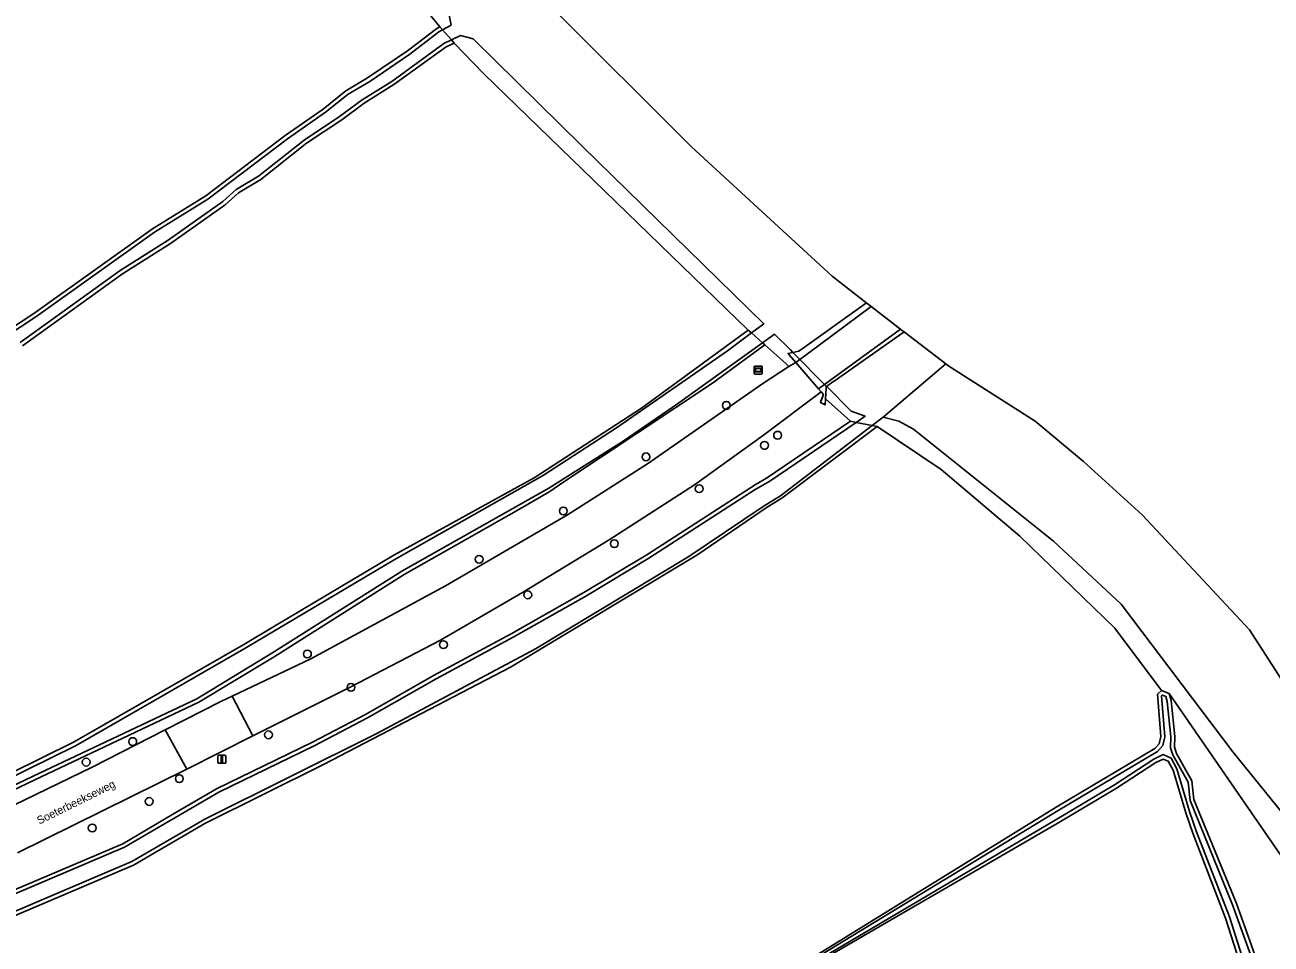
# Model space of a CAD drawing. Extents: x 162396 to 163643, y 386452 to 387406.
# Drawn here: x 163407.9 to 163563.6, y 386571.8 to 386686.7 of the extents above; entities that cross this region are included whole.
import ezdxf

# ---------------------------------------------------------------- set-up
doc = ezdxf.new("R2010")
doc.units = 0
for name, color, linetype in [('IMGEO_Berm_groen', 7, 'Continuous'), ('IMGEO_Boom', 7, 'Continuous'), ('IMGEO_Greppel_droge_sloot', 7, 'Continuous'), ('IMGEO_Lichtmast', 7, 'Continuous'), ('IMGEO_Loofbos', 7, 'Continuous'), ('IMGEO_Oever', 7, 'Continuous'), ('IMGEO_Openbare_ruimte_label', 7, 'Continuous'), ('IMGEO_Rijbaan_lokaal_gesloten', 7, 'Continuous'), ('IMGEO_Rijbaan_lokaal_open', 7, 'Continuous'), ('IMGEO_Rivier', 7, 'Continuous'), ('IMGEO_Terreindeel_gesloten', 7, 'Continuous'), ('IMGEO_Waterloop', 7, 'Continuous'), ('IMGEO_Wegwijzer', 7, 'Continuous')]:
    doc.layers.add(name, color=color, linetype=linetype)

msp = doc.modelspace()

# ---------------------------------------------------------------- linework, layer by layer
at = {"layer": 'IMGEO_Berm_groen'}
for points in [[(163405.11, 386588.52), (163416.26, 386593.91), (163425.38, 386598.57), (163432.36, 386602.14), (163433.75, 386602.8), (163443.58, 386607.46), (163460.42, 386616.57), (163475.67, 386625.45), (163485.67, 386631.81), (163500.08, 386641.88), (163503.35, 386643.97), (163502.95, 386644.35), (163500.35, 386646.68), (163493.79, 386641.9), (163475.22, 386629.59), (163473.48, 386628.39), (163469.61, 386626.14), (163455.26, 386617.99), (163439.01, 386607.73), (163429.6, 386602.04), (163409.1, 386592.34), (163397.9, 386587.01)], [(163401.51, 386576.46), (163420.09, 386584.36), (163426.24, 386587.96), (163431.82, 386591.22), (163443.79, 386597.04), (163450.45, 386600.52), (163459.01, 386605.41), (163468.63, 386610.6), (163477.72, 386615.74), (163485.57, 386620.45), (163499.26, 386629.28), (163500.56, 386630.02), (163511.05, 386637.15), (163507.93, 386639.95), (163507.88, 386639.21), (163507.28, 386639.5), (163507.65, 386640.51), (163507.39, 386640.81), (163500.18, 386635.41), (163491.54, 386629.21), (163480.87, 386622.34), (163470.05, 386615.73), (163459.8, 386609.81), (163448.52, 386603.94), (163436.36, 386597.86), (163428.09, 386593.69), (163406.94, 386583.2)]]:
    msp.add_lwpolyline(points, dxfattribs=at)
at = {"layer": 'IMGEO_Boom'}
for centre in [(163495.52, 386639.13), (163501.93, 386635.4), (163485.49, 386632.7), (163500.29, 386634.13), (163492.13, 386628.72), (163475.16, 386625.93), (163481.52, 386621.85), (163464.63, 386619.9), (163470.71, 386615.46), (163443.17, 386608.07), (163460.17, 386609.23), (163448.61, 386603.9), (163421.34, 386597.12), (163438.3, 386597.97), (163415.52, 386594.55), (163427.17, 386592.49), (163423.4, 386589.64), (163416.28, 386586.33)]:
    msp.add_circle(centre, 0.489, dxfattribs=at)
at = {"layer": 'IMGEO_Greppel_droge_sloot'}
msp.add_lwpolyline([(163562.37, 386566.81), (163558.8, 386576.71), (163553.47, 386589.78), (163553.22, 386592.06), (163551.32, 386595.45), (163551.05, 386596.36), (163551.08, 386597.73), (163550.63, 386602.14), (163550.45, 386602.75), (163550.02, 386602.92), (163549.91, 386602.82), (163550.34, 386597.72), (163550.07, 386596.62), (163549.41, 386595.88), (163537.01, 386588.49), (163506.56, 386569.96)], dxfattribs=at)
msp.add_lwpolyline([(163455.86, 386538.91), (163459.42, 386541.07), (163473.79, 386549.33), (163480.21, 386553.86), (163490.62, 386559.9), (163500.01, 386565.64), (163504.86, 386568.54), (163536.63, 386587.32), (163544.03, 386591.71), (163548.94, 386594.93), (163550.11, 386595.49), (163551.11, 386595.06), (163551.84, 386593.72), (163553.42, 386588.37), (163554.3, 386585.83), (163558.39, 386575.21), (163562.24, 386563.11), (163561.91, 386561.81), (163543.3, 386550.61), (163516, 386533.9), (163499.96, 386535.01), (163489.08, 386535.89), (163478.15, 386536.57)], close=True, dxfattribs=at)
at = {"layer": 'IMGEO_Lichtmast'}
for p, q in [((163431.99, 386594.51), (163431.99, 386595.31)), ((163431.99, 386595.31), (163431.99, 386594.51)), ((163432.09, 386595.41), (163432.88, 386595.41)), ((163432.88, 386595.41), (163432.09, 386595.41)), ((163432.88, 386594.41), (163432.09, 386594.41)), ((163432.09, 386594.41), (163432.88, 386594.41)), ((163432.98, 386595.31), (163432.98, 386594.51)), ((163432.98, 386594.51), (163432.98, 386595.31))]:
    msp.add_line(p, q, dxfattribs=at)
msp.add_lwpolyline([(163432.41, 386595.29), (163432.56, 386595.29), (163432.56, 386594.54), (163432.41, 386594.54), (163432.41, 386595.29)], dxfattribs=at)
for centre, start, end in [((163432.09, 386595.31), 90, 180), ((163432.09, 386595.31), 90, 180), ((163432.09, 386594.51), 180, 270), ((163432.09, 386594.51), 180, 270), ((163432.88, 386595.31), 0, 90), ((163432.88, 386595.31), 360, 90), ((163432.88, 386594.51), 270, 0), ((163432.88, 386594.51), 270, 0)]:
    msp.add_arc(centre, 0.1, start, end, dxfattribs=at)
at = {"layer": 'IMGEO_Loofbos'}
for points in [[(163391.4, 386639.08), (163408.96, 386650.61), (163423.8, 386661.18), (163430.46, 386665.33), (163440.39, 386672.86), (163445.14, 386676.15), (163447.97, 386678.44), (163450.69, 386680.05), (163455.66, 386683.43), (163459.34, 386686.22), (163459.71, 386686.42), (163457.27, 386689.42)], [(163402.02, 386591.16), (163413.94, 386597.03), (163417.16, 386598.88), (163435.23, 386609.26), (163439.05, 386611.53), (163453.98, 386620.4), (163471.52, 386630.07), (163484.91, 386638.8), (163498.26, 386648.53), (163465.17, 386680.6), (163461.52, 386684.41), (163460.49, 386683.93), (163453.99, 386679.21), (163450.28, 386676.89), (163447.46, 386674.82), (163443.07, 386671.89), (163437.34, 386667.34), (163434.55, 386665.69), (163432.89, 386664.21), (163426.04, 386659.35), (163420.06, 386655.56), (163407.55, 386646.58)], [(163506.44, 386570.22), (163536.75, 386588.92), (163549.09, 386596.27), (163549.61, 386596.86), (163549.83, 386597.76), (163549.39, 386603.03), (163549.92, 386603.5), (163544.07, 386611.28), (163532.19, 386622.81), (163522.36, 386631.11), (163514.36, 386636.48), (163502.48, 386627.54), (163500.63, 386626.43), (163491.82, 386620.43), (163468.54, 386606.44), (163445.2, 386594.24), (163430.35, 386586.89), (163421.44, 386581.67), (163402.62, 386573.67)]]:
    msp.add_lwpolyline(points, dxfattribs=at)
for points in [[(163550.86, 386603.13), (163551.12, 386602.24), (163551.58, 386597.75), (163551.55, 386596.43), (163551.79, 386595.64), (163553.71, 386592.21), (163553.96, 386589.9), (163559.27, 386576.89), (163562.84, 386566.97), (163566.19, 386556.37), (163567.14, 386552.77), (163574.75, 386529.67), (163593.86, 386541.96), (163569.34, 386576.39)], [(163478.18, 386537.07), (163489.12, 386536.39), (163500, 386535.51), (163515.87, 386534.41), (163543.04, 386551.04), (163561.47, 386562.13), (163561.72, 386563.1), (163557.92, 386575.04), (163553.83, 386585.66), (163552.94, 386588.22), (163551.38, 386593.53), (163550.76, 386594.67), (163550.12, 386594.94), (163549.18, 386594.5), (163544.29, 386591.29), (163536.88, 386586.89), (163505.12, 386568.46), (163500, 386565.34), (163490.87, 386559.78), (163480.45, 386553.87), (163473.95, 386549.09), (163459.51, 386540.9), (163456.65, 386539.08)]]:
    msp.add_lwpolyline(points, close=True, dxfattribs=at)
at = {"layer": 'IMGEO_Oever'}
for points in [[(163457.27, 386689.42), (163459.71, 386686.42), (163460.05, 386686.04), (163461.12, 386686.65), (163460.87, 386687.9)], [(163391.68, 386638.67), (163409.24, 386650.2), (163424.08, 386660.77), (163430.74, 386664.92), (163440.68, 386672.45), (163445.44, 386675.75), (163448.26, 386678.03), (163450.96, 386679.62), (163455.96, 386683.02), (163459.61, 386685.8), (163460.05, 386686.04), (163459.71, 386686.42), (163459.34, 386686.22), (163455.66, 386683.43), (163450.69, 386680.05), (163447.97, 386678.44), (163445.14, 386676.15), (163440.39, 386672.86), (163430.46, 386665.33), (163423.8, 386661.18), (163408.96, 386650.61), (163391.4, 386639.08)], [(163407.55, 386646.58), (163420.06, 386655.56), (163426.04, 386659.35), (163432.89, 386664.21), (163434.55, 386665.69), (163437.34, 386667.34), (163443.07, 386671.89), (163447.46, 386674.82), (163450.28, 386676.89), (163453.99, 386679.21), (163460.49, 386683.93), (163461.52, 386684.41), (163461.17, 386684.8), (163460.23, 386684.36), (163453.71, 386679.62), (163450, 386677.31), (163447.18, 386675.23), (163442.78, 386672.29), (163437.06, 386667.76), (163434.26, 386666.1), (163432.58, 386664.6), (163425.76, 386659.77), (163419.78, 386655.97), (163407.28, 386647)], [(163402.22, 386590.71), (163414.18, 386596.59), (163423.97, 386602.22), (163435.48, 386608.82), (163454.24, 386619.97), (163472.54, 386630.34), (163481.79, 386636.31), (163495.67, 386645.94), (163498.66, 386648.18), (163498.26, 386648.53), (163484.91, 386638.8), (163471.52, 386630.07), (163453.98, 386620.4), (163439.05, 386611.53), (163435.23, 386609.26), (163417.16, 386598.88), (163413.94, 386597.03), (163402.02, 386591.16)], [(163397.9, 386587.01), (163409.1, 386592.34), (163429.6, 386602.04), (163439.01, 386607.73), (163455.26, 386617.99), (163469.61, 386626.14), (163473.48, 386628.39), (163475.22, 386629.59), (163493.79, 386641.9), (163500.35, 386646.68), (163500.04, 386646.96), (163489.41, 386639.33), (163482.61, 386634.67), (163473.36, 386628.8), (163454.99, 386618.41), (163438.74, 386608.16), (163429.36, 386602.48), (163408.88, 386592.79), (163397.7, 386587.47)], [(163401.7, 386576), (163420.31, 386583.91), (163432.08, 386590.79), (163444.02, 386596.59), (163450.69, 386600.08), (163459.25, 386604.97), (163468.87, 386610.16), (163477.97, 386615.31), (163485.83, 386620.03), (163499.13, 386628.6), (163500.95, 386629.68), (163511.73, 386637.01), (163511.05, 386637.15), (163500.56, 386630.02), (163499.26, 386629.28), (163485.57, 386620.45), (163477.72, 386615.74), (163468.63, 386610.6), (163459.01, 386605.41), (163450.45, 386600.52), (163443.79, 386597.04), (163431.82, 386591.22), (163426.24, 386587.96), (163420.09, 386584.36), (163401.51, 386576.46)], [(163402.62, 386573.67), (163421.44, 386581.67), (163430.35, 386586.89), (163445.2, 386594.24), (163468.54, 386606.44), (163491.82, 386620.43), (163500.63, 386626.43), (163502.48, 386627.54), (163514.36, 386636.48), (163513.76, 386636.6), (163502.29, 386627.82), (163500.45, 386626.7), (163500, 386626.4), (163490.83, 386620.24), (163471.67, 386608.7), (163451.85, 386598.12), (163430.36, 386587.44), (163421.21, 386582.12), (163402.44, 386574.14)], [(163562.84, 386566.97), (163559.27, 386576.89), (163553.96, 386589.9), (163553.71, 386592.21), (163551.79, 386595.64), (163551.55, 386596.43), (163551.58, 386597.75), (163551.12, 386602.24), (163550.86, 386603.13), (163549.92, 386603.5), (163549.39, 386603.03), (163549.83, 386597.76), (163549.61, 386596.86), (163549.09, 386596.27), (163536.75, 386588.92), (163506.44, 386570.22)], [(163506.56, 386569.96), (163537.01, 386588.49), (163549.41, 386595.88), (163550.07, 386596.62), (163550.34, 386597.72), (163549.91, 386602.82), (163550.02, 386602.92), (163550.45, 386602.75), (163550.63, 386602.14), (163551.08, 386597.73), (163551.05, 386596.36), (163551.32, 386595.45), (163553.22, 386592.06), (163553.47, 386589.78), (163558.8, 386576.71), (163562.37, 386566.81)]]:
    msp.add_lwpolyline(points, dxfattribs=at)
for points in [[(163463.9, 386684.93), (163462.31, 386685.33), (163461.17, 386684.8), (163461.52, 386684.41), (163465.17, 386680.6), (163498.26, 386648.53), (163498.66, 386648.18), (163500.21, 386649.34), (163477.47, 386671.58)], [(163501.54, 386648.03), (163500.04, 386646.96), (163500.35, 386646.68), (163502.95, 386644.35), (163503.35, 386643.97), (163504.2, 386644.51), (163507.05, 386641.2), (163507.39, 386640.81), (163507.65, 386640.51), (163507.28, 386639.5), (163507.88, 386639.21), (163507.93, 386639.95), (163511.05, 386637.15), (163511.73, 386637.01), (163512.86, 386637.78), (163511.14, 386638.39), (163508.08, 386641.49), (163508.06, 386641.51), (163503.85, 386645.76), (163503.55, 386646.07)], [(163518.9, 386636.15), (163517.08, 386637.18), (163515.13, 386637.65), (163513.76, 386636.6), (163514.36, 386636.48), (163522.36, 386631.11), (163532.19, 386622.81), (163544.07, 386611.28), (163549.92, 386603.5), (163550.86, 386603.13), (163569.34, 386576.39), (163593.86, 386541.96), (163594.43, 386541.13), (163605.08, 386527.79), (163605.32, 386525.72), (163612.1, 386524.92), (163587.38, 386560.56), (163558.82, 386595.86), (163544.88, 386614.29), (163536.39, 386622.18)], [(163455.86, 386538.91), (163478.15, 386536.57), (163489.08, 386535.89), (163499.96, 386535.01), (163516, 386533.9), (163543.3, 386550.61), (163561.91, 386561.81), (163562.24, 386563.11), (163558.39, 386575.21), (163554.3, 386585.83), (163553.42, 386588.37), (163551.84, 386593.72), (163551.11, 386595.06), (163550.11, 386595.49), (163548.94, 386594.93), (163544.03, 386591.71), (163536.63, 386587.32), (163504.86, 386568.54), (163500.01, 386565.64), (163490.62, 386559.9), (163480.21, 386553.86), (163473.79, 386549.33), (163459.42, 386541.07)], [(163561.72, 386563.1), (163561.47, 386562.13), (163543.04, 386551.04), (163515.87, 386534.41), (163500, 386535.51), (163489.12, 386536.39), (163478.18, 386537.07), (163456.65, 386539.08), (163459.51, 386540.9), (163473.95, 386549.09), (163480.45, 386553.87), (163490.87, 386559.78), (163500, 386565.34), (163505.12, 386568.46), (163536.88, 386586.89), (163544.29, 386591.29), (163549.18, 386594.5), (163550.12, 386594.94), (163550.76, 386594.67), (163551.38, 386593.53), (163552.94, 386588.22), (163553.83, 386585.66), (163557.92, 386575.04)]]:
    msp.add_lwpolyline(points, close=True, dxfattribs=at)
at = {"layer": 'IMGEO_Rijbaan_lokaal_gesloten'}
msp.add_lwpolyline([(163517.29, 386648.67), (163513.64, 386651.47), (163504.2, 386644.51), (163507.05, 386641.2)], close=True, dxfattribs=at)
msp.add_lwpolyline([(163406.94, 386583.2), (163428.09, 386593.69), (163425.38, 386598.57), (163416.26, 386593.91), (163405.11, 386588.52)], dxfattribs=at)
at = {"layer": 'IMGEO_Rijbaan_lokaal_open'}
for points in [[(163480.87, 386622.34), (163491.54, 386629.21), (163500.18, 386635.41), (163507.39, 386640.81), (163507.05, 386641.2), (163504.2, 386644.51), (163503.35, 386643.97), (163500.08, 386641.88), (163485.67, 386631.81), (163475.67, 386625.45), (163460.42, 386616.57), (163443.58, 386607.46), (163433.75, 386602.8), (163436.36, 386597.86), (163448.52, 386603.94), (163459.8, 386609.81), (163470.05, 386615.73)], [(163433.75, 386602.8), (163432.36, 386602.14), (163425.38, 386598.57), (163428.09, 386593.69), (163436.36, 386597.86)]]:
    msp.add_lwpolyline(points, close=True, dxfattribs=at)
at = {"layer": 'IMGEO_Rivier'}
for points in [[(163460.87, 386687.9), (163461.12, 386686.65), (163460.05, 386686.04), (163461.17, 386684.8), (163462.31, 386685.33), (163463.9, 386684.93), (163477.47, 386671.58), (163500.21, 386649.34), (163498.66, 386648.18), (163500.04, 386646.96), (163501.54, 386648.03), (163503.55, 386646.07), (163503.85, 386645.76), (163508.06, 386641.51), (163508.08, 386641.49), (163511.14, 386638.39), (163512.86, 386637.78), (163511.73, 386637.01), (163513.76, 386636.6), (163515.13, 386637.65), (163522.94, 386644.32), (163517.78, 386648.29), (163517.39, 386648.59), (163513.59, 386651.51), (163513.13, 386651.87), (163508.76, 386655.27), (163500, 386663.32), (163491.19, 386671.42), (163473.62, 386688.94)], [(163522.94, 386644.32), (163515.13, 386637.65), (163517.08, 386637.18), (163518.9, 386636.15), (163536.39, 386622.18), (163544.88, 386614.29), (163558.82, 386595.86), (163587.38, 386560.56)], [(163568.08, 386599.98), (163560.89, 386611.1), (163547.51, 386625.44), (163540.16, 386632.14), (163534.1, 386637.17), (163523.19, 386644.13), (163522.94, 386644.32)]]:
    msp.add_lwpolyline(points, dxfattribs=at)
at = {"layer": 'IMGEO_Terreindeel_gesloten'}
for points in [[(163513.64, 386651.47), (163513.59, 386651.51), (163513.13, 386651.87), (163513.03, 386651.95), (163505.01, 386646.21), (163504.58, 386645.91), (163503.85, 386645.76), (163503.24, 386645.63), (163503.38, 386645.46), (163504.2, 386644.51)], [(163517.74, 386648.32), (163517.39, 386648.59), (163517.29, 386648.67), (163507.05, 386641.2), (163507.65, 386640.51), (163507.39, 386639.8), (163507.28, 386639.5), (163507.88, 386639.21), (163507.93, 386639.95), (163508.01, 386641.25), (163508.02, 386641.48), (163508.06, 386641.51), (163508.85, 386642.06), (163508.98, 386642.15)]]:
    msp.add_lwpolyline(points, close=True, dxfattribs=at)
at = {"layer": 'IMGEO_Waterloop'}
for points in [[(163407.28, 386647), (163419.78, 386655.97), (163425.76, 386659.77), (163432.58, 386664.6), (163434.26, 386666.1), (163437.06, 386667.76), (163442.78, 386672.29), (163447.18, 386675.23), (163450, 386677.31), (163453.71, 386679.62), (163460.23, 386684.36), (163461.17, 386684.8), (163460.05, 386686.04), (163459.61, 386685.8), (163455.96, 386683.02), (163450.96, 386679.62), (163448.26, 386678.03), (163445.44, 386675.75), (163440.68, 386672.45), (163430.74, 386664.92), (163424.08, 386660.77), (163409.24, 386650.2), (163391.68, 386638.67)], [(163397.7, 386587.47), (163408.88, 386592.79), (163429.36, 386602.48), (163438.74, 386608.16), (163454.99, 386618.41), (163473.36, 386628.8), (163482.61, 386634.67), (163489.41, 386639.33), (163500.04, 386646.96), (163498.66, 386648.18), (163495.67, 386645.94), (163481.79, 386636.31), (163472.54, 386630.34), (163454.24, 386619.97), (163435.48, 386608.82), (163423.97, 386602.22), (163414.18, 386596.59), (163402.22, 386590.71)], [(163402.44, 386574.14), (163421.21, 386582.12), (163430.36, 386587.44), (163451.85, 386598.12), (163471.67, 386608.7), (163490.83, 386620.24), (163500, 386626.4), (163500.45, 386626.7), (163502.29, 386627.82), (163513.76, 386636.6), (163511.73, 386637.01), (163500.95, 386629.68), (163499.13, 386628.6), (163485.83, 386620.03), (163477.97, 386615.31), (163468.87, 386610.16), (163459.25, 386604.97), (163450.69, 386600.08), (163444.02, 386596.59), (163432.08, 386590.79), (163420.31, 386583.91), (163401.7, 386576)]]:
    msp.add_lwpolyline(points, dxfattribs=at)
at = {"layer": 'IMGEO_Wegwijzer'}
for p, q in [((163499.02, 386643.15), (163499.02, 386643.95)), ((163499.02, 386643.95), (163499.02, 386643.15)), ((163499.12, 386644.05), (163499.9, 386644.05)), ((163499.9, 386644.05), (163499.12, 386644.05)), ((163499.9, 386643.05), (163499.12, 386643.05)), ((163499.12, 386643.05), (163499.9, 386643.05)), ((163500, 386643.95), (163500, 386643.15)), ((163500, 386643.15), (163500, 386643.95))]:
    msp.add_line(p, q, dxfattribs=at)
for points in [[(163499.12, 386643.78), (163499.9, 386643.78), (163499.9, 386643.32), (163499.12, 386643.32), (163499.12, 386643.78)], [(163499.18, 386643.72), (163499.18, 386643.38), (163499.84, 386643.38), (163499.84, 386643.72), (163499.18, 386643.72)]]:
    msp.add_lwpolyline(points, dxfattribs=at)
for centre, start, end in [((163499.12, 386643.95), 90, 180), ((163499.12, 386643.95), 90, 180), ((163499.12, 386643.15), 180, 270), ((163499.12, 386643.15), 180, 270), ((163499.9, 386643.95), 0, 90), ((163499.9, 386643.95), 360, 90), ((163499.9, 386643.15), 270, 0), ((163499.9, 386643.15), 270, 0)]:
    msp.add_arc(centre, 0.1, start, end, dxfattribs=at)

# ---------------------------------------------------------------- texts
at = {"layer": 'IMGEO_Openbare_ruimte_label'}
msp.add_text('Soeterbeekseweg', height=1, rotation=26.2833, dxfattribs=at).set_placement((163409.67, 386586.74))

doc.saveas('drawing.dxf')
